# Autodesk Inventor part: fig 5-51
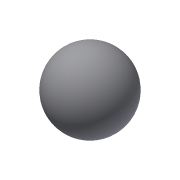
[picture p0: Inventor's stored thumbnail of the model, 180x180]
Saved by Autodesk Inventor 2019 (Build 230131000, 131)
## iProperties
Created: 2012-07
Part Number: fig 5-51
Material: Generic
Document SubType Name: Modeling
Designer: CADCIM
Density: 1 g/cm^3
Appearance: Default
Author: CADCIM
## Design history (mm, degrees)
sketch "Sketch1"
  geometry: L1 (7.807, -5.174)-(-7.807, 5.174); A1 r 9.366 centre (0, 0) between (7.807, -5.174) and (-7.807, 5.174)
  constraints: 2 end point, 2 point on circle, 1 centre point, 1 midpoint
revolve "Revolution1" sketch "Sketch1" stored, may be unused: angle "d0" = 90 deg
workpoint "Work Point1"
body "Solid1"
